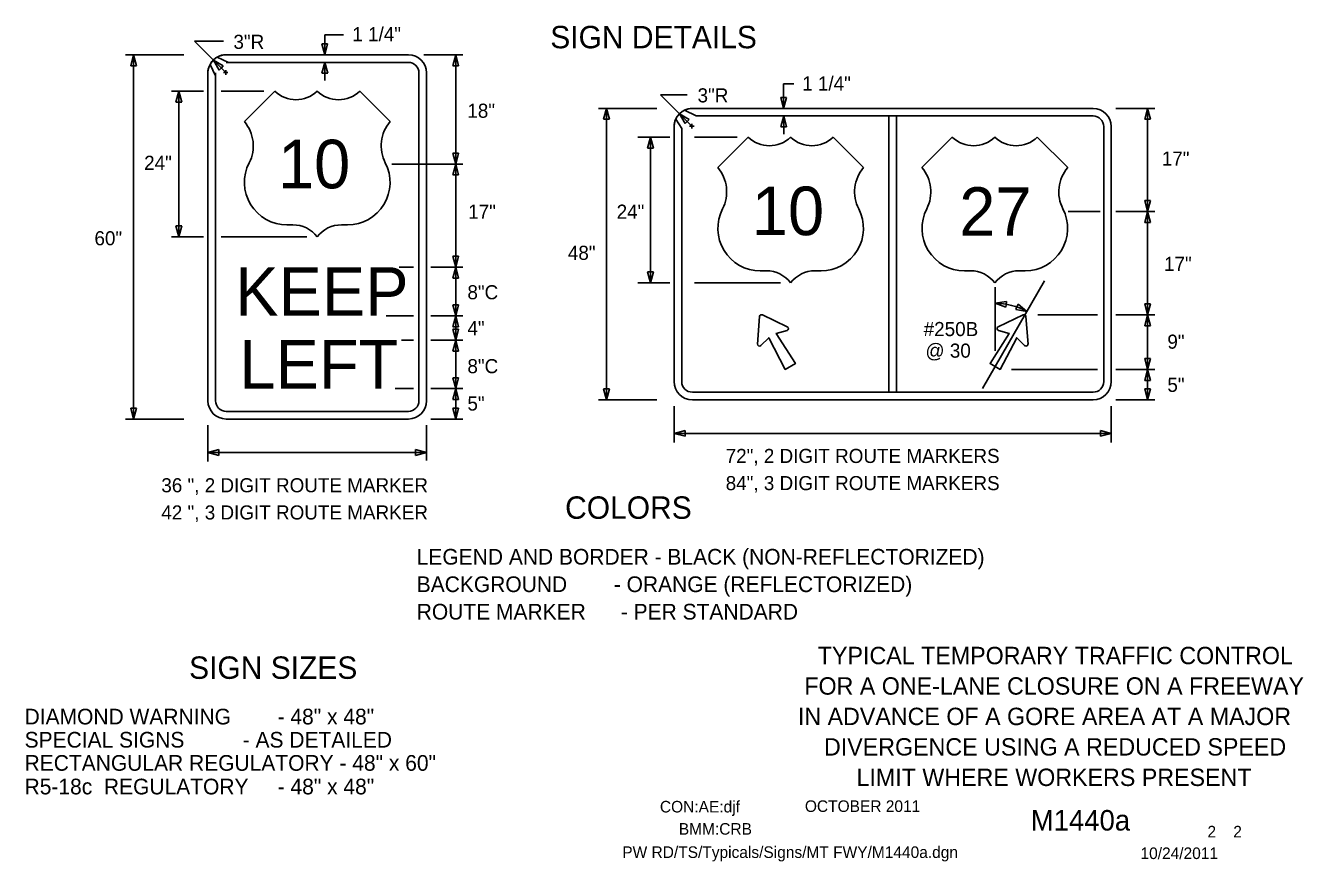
# Model space of a CAD drawing. Extents: x 16731 to 18464, y 5737 to 6974.
# Drawn here: x 17780 to 18464, y 5932 to 6379 of the extents above; entities that cross this region are included whole.
import ezdxf

# ---------------------------------------------------------------- set-up
doc = ezdxf.new("R2010")
doc.units = 0
for name, color, linetype in [('BORDER', 7, 'Continuous'), ('BORDER_SIGNAL_WO', 7, 'Continuous'), ('TRAFFIC_SIGNS_PR', 7, 'Continuous'), ('TYPICAL_EX', 7, 'Continuous'), ('TYPICAL_TEXT_DIMEN_PR', 7, 'Continuous')]:
    doc.layers.add(name, color=color, linetype=linetype)

msp = doc.modelspace()

# ---------------------------------------------------------------- linework, layer by layer
at = {"layer": 'TRAFFIC_SIGNS_PR'}
for p, q in [((17888.74, 6359.64), (17882.64, 6362.38)), ((17887.54, 6363.7), (17985.04, 6363.7)), ((17879.95, 6360.08), (17878.95, 6358.57)), ((17878.98, 6358.5), (17881.85, 6352.46)), ((17985.04, 6359.64), (17887.54, 6359.64)), ((17877.79, 6178.45), (17877.79, 6353.95)), ((17881.85, 6353.95), (17881.85, 6178.45)), ((17990.72, 6178.45), (17990.72, 6353.95)), ((17994.79, 6353.95), (17994.79, 6178.45)), ((18139.01, 6330.95), (18132.78, 6333.97)), ((18137.06, 6335), (18351.56, 6335)), ((18137.06, 6335), (18351.56, 6335)), ((18128.23, 6329.26), (18131.37, 6324.21)), ((18138.99, 6330.94), (18242.28, 6330.94)), ((18351.56, 6330.94), (18139, 6330.94)), ((18242.28, 6330.94), (18242.28, 6183.06)), ((18246.34, 6330.94), (18246.34, 6183.06)), ((18246.34, 6330.94), (18351.56, 6330.94)), ((18127.31, 6325.25), (18127.31, 6188.75)), ((18127.31, 6188.75), (18127.31, 6325.25)), ((18131.37, 6324.2), (18131.37, 6188.75)), ((18131.37, 6324.2), (18131.37, 6188.75)), ((18357.24, 6325.25), (18357.24, 6279.5)), ((18357.25, 6188.75), (18357.25, 6325.25)), ((18361.31, 6325.25), (18361.31, 6188.75)), ((18361.31, 6325.25), (18361.31, 6188.75)), ((18357.24, 6279.5), (18357.24, 6188.75)), ((18174.57, 6224.44), (18187.89, 6218.08)), ((18314.04, 6224.44), (18300.73, 6218.08)), ((18171.91, 6208.86), (18173.06, 6223.57)), ((18316.71, 6208.86), (18315.56, 6223.57)), ((18137.06, 6183.06), (18351.56, 6183.06)), ((18137.06, 6179), (18351.56, 6179)), ((18351.56, 6179), (18137.06, 6179)), ((17887.54, 6172.76), (17985.04, 6172.76)), ((17985.04, 6168.7), (17887.54, 6168.7))]:
    msp.add_line(p, q, dxfattribs=at)
for points in [[(18139, 6330.94), (18138.98, 6330.94)], [(18131.37, 6324.21), (18131.37, 6324.2)], [(18187.73, 6216.11), (18182, 6214.54), (18192.22, 6198.37), (18186.82, 6195.25), (18177.93, 6212.19), (18173.7, 6208.02)], [(18300.89, 6216.11), (18306.61, 6214.54), (18296.4, 6198.37), (18301.79, 6195.25), (18310.69, 6212.19), (18314.91, 6208.02)]]:
    msp.add_lwpolyline(points, dxfattribs=at)
msp.add_lwpolyline([(18242.28, 6330.94), (18246.34, 6330.94), (18246.34, 6183.06), (18242.28, 6183.06)], close=True, dxfattribs=at)
for centre, radius, start, end in [((17887.54, 6353.95), 9.75, 90, 180), ((17886.95, 6356.12), 7.6, 85.58319, 124.53531), ((17985.04, 6353.95), 9.75, 0, 90), ((17884.82, 6354.54), 7.06, 145.86811, 184.82317), ((17888.14, 6364.06), 4.47, 262.2432, 277.7568), ((17985.04, 6353.95), 5.69, 0, 90), ((17876.39, 6353.2), 5.51, 352.24294, 7.75653), ((18137.06, 6325.25), 9.75, 90, 180), ((18137.06, 6325.25), 9.75, 90, 180), ((18136.38, 6328.43), 6.6, 84.11162, 123.06374), ((18351.56, 6325.25), 9.75, 0, 90), ((18351.56, 6325.25), 9.75, 0, 90), ((18133.44, 6325.95), 6.17, 147.60925, 186.56283), ((18138, 6338.12), 7.24, 277.81035, 278.05403), ((18351.56, 6325.25), 5.69, 0, 89.99421), ((18351.56, 6325.25), 5.69, 0, 90), ((18174.12, 6223.49), 1.06, 64.48226, 175.51774), ((18314.5, 6223.49), 1.06, 4.48226, 115.51774), ((18187.43, 6217.13), 1.06, 285.9885, 64.48226), ((18301.18, 6217.13), 1.06, 115.51774, 254.0115), ((18172.97, 6208.78), 1.06, 175.51775, 314.01151), ((18315.65, 6208.78), 1.06, 225.98849, 4.48225), ((18137.06, 6188.75), 9.75, 180, 270), ((18137.06, 6188.75), 9.75, 180, 270), ((18137.06, 6188.75), 5.69, 180, 270), ((18137.06, 6188.75), 5.69, 180, 270), ((18351.56, 6188.75), 9.75, 270, 0), ((18351.56, 6188.75), 5.69, 270, 0), ((18351.56, 6188.75), 9.75, 270, 0), ((18351.56, 6188.75), 5.69, 270, 0), ((17887.54, 6178.45), 9.75, 180, 270), ((17887.54, 6178.45), 5.69, 180, 270), ((17985.04, 6178.45), 5.69, 270, 0), ((17985.04, 6178.45), 9.75, 270, 0)]:
    msp.add_arc(centre, radius, start, end, dxfattribs=at)
at = {"layer": 'TYPICAL_EX'}
for p, q in [((17897.29, 6327.95), (17913.54, 6344.2)), ((17975.29, 6327.95), (17959.04, 6344.2)), ((18150.67, 6303.34), (18166.92, 6319.59)), ((18228.67, 6303.34), (18212.42, 6319.59)), ((18259.95, 6303.34), (18276.2, 6319.59)), ((18337.95, 6303.34), (18321.7, 6319.59)), ((17920.01, 6272.66), (17923.26, 6272.66)), ((17952.56, 6272.66), (17949.31, 6272.66)), ((18173.4, 6248.05), (18176.65, 6248.05)), ((18205.94, 6248.05), (18202.69, 6248.05)), ((18282.67, 6248.05), (18285.92, 6248.05)), ((18315.22, 6248.05), (18311.97, 6248.05))]:
    msp.add_line(p, q, dxfattribs=at)
for centre, radius, start, end in [((17924.91, 6356.03), 16.42, 226.14041, 313.85958), ((17947.66, 6356.04), 16.42, 226.14042, 313.85959), ((17881.88, 6314.94), 20.16, 333.09768, 40.19361), ((17990.69, 6314.94), 20.16, 139.80639, 206.90233), ((18178.3, 6331.42), 16.42, 226.14041, 313.85958), ((18201.04, 6331.43), 16.42, 226.14042, 313.85959), ((18287.57, 6331.42), 16.42, 226.14041, 313.85958), ((18310.32, 6331.43), 16.42, 226.14042, 313.85959), ((17920.05, 6295.38), 22.73, 152.6698, 269.90132), ((17952.52, 6295.38), 22.73, 270.09868, 27.3302), ((18135.27, 6290.33), 20.16, 333.09768, 40.19361), ((18244.07, 6290.33), 20.16, 139.80639, 206.90233), ((18244.55, 6290.33), 20.16, 333.09768, 40.19361), ((18353.35, 6290.33), 20.16, 139.80639, 206.90233), ((18173.44, 6270.77), 22.73, 152.6698, 269.90132), ((18205.9, 6270.77), 22.73, 270.09868, 27.3302), ((18282.71, 6270.77), 22.73, 152.6698, 269.90132), ((18315.18, 6270.77), 22.73, 270.09868, 27.3302), ((17923.3, 6256.38), 16.28, 37.1038, 90.13853), ((17949.27, 6256.38), 16.28, 89.86147, 142.8962), ((18176.69, 6231.77), 16.28, 37.1038, 90.13853), ((18202.65, 6231.77), 16.28, 89.86147, 142.8962), ((18285.97, 6231.77), 16.28, 37.1038, 90.13853), ((18311.93, 6231.77), 16.28, 89.86147, 142.8962)]:
    msp.add_arc(centre, radius, start, end, dxfattribs=at)
at = {"layer": 'TYPICAL_TEXT_DIMEN_PR'}
for p, q in [((17886.16, 6370.98), (17870.5, 6370.98)), ((17870.5, 6370.98), (17880.74, 6360.74)), ((17940.26, 6363.7), (17938.69, 6369.56)), ((17938.69, 6369.56), (17940.26, 6369.56)), ((17940.26, 6374.46), (17940.26, 6363.7)), ((17940.26, 6374.46), (17950.36, 6374.46)), ((17940.26, 6369.56), (17941.83, 6369.56)), ((17941.83, 6369.56), (17940.26, 6363.7)), ((17864.96, 6363.7), (17833.66, 6363.7)), ((17836.43, 6357.84), (17838, 6363.7)), ((17838, 6363.7), (17838, 6168.7)), ((17838, 6363.7), (17839.57, 6357.84)), ((17993.33, 6363.7), (18014.29, 6363.7)), ((18008.82, 6357.84), (18010.39, 6363.7)), ((18010.39, 6363.7), (18010.39, 6305.2)), ((18010.39, 6363.7), (18011.96, 6357.84)), ((17838, 6357.84), (17836.43, 6357.84)), ((17839.57, 6357.84), (17838, 6357.84)), ((17880.74, 6360.74), (17887.3, 6354.19)), ((17883.77, 6355.49), (17880.74, 6360.74)), ((17880.74, 6360.74), (17885.99, 6357.71)), ((17884.88, 6356.6), (17883.77, 6355.49)), ((17885.99, 6357.71), (17884.88, 6356.6)), ((17886.09, 6354.19), (17888.5, 6354.19)), ((17887.3, 6352.98), (17887.3, 6355.4)), ((17938.74, 6353.77), (17940.31, 6359.64)), ((17940.31, 6359.64), (17940.31, 6349.89)), ((17940.31, 6359.64), (17941.88, 6353.77)), ((18010.39, 6357.84), (18008.82, 6357.84)), ((18011.96, 6357.84), (18010.39, 6357.84)), ((17940.31, 6353.77), (17938.74, 6353.77)), ((17941.88, 6353.77), (17940.31, 6353.77)), ((18185.92, 6348.15), (18185.92, 6335)), ((18185.92, 6348.15), (18191.44, 6348.15)), ((17875.41, 6344.2), (17858.29, 6344.2)), ((17860.61, 6338.34), (17862.18, 6344.2)), ((17862.18, 6344.2), (17862.18, 6266.2)), ((17862.18, 6344.2), (17863.75, 6338.34)), ((17907.65, 6344.2), (17884.78, 6344.2)), ((18134.2, 6342.28), (18120.02, 6342.28)), ((18120.02, 6342.28), (18130.17, 6332.14)), ((18185.92, 6335), (18184.34, 6340.86)), ((18184.34, 6340.86), (18185.92, 6340.86)), ((18185.92, 6340.86), (18187.49, 6340.86)), ((18187.49, 6340.86), (18185.92, 6335)), ((17862.18, 6338.34), (17860.61, 6338.34)), ((17863.75, 6338.34), (17862.18, 6338.34)), ((18118.08, 6335), (18086.78, 6335)), ((18089.55, 6329.14), (18091.12, 6335)), ((18091.12, 6335), (18091.12, 6179)), ((18091.12, 6335), (18092.69, 6329.14)), ((18363.68, 6335), (18384.64, 6335)), ((18379.17, 6329.14), (18380.74, 6335)), ((18380.74, 6335), (18380.74, 6279.75)), ((18380.74, 6335), (18382.31, 6329.14)), ((18091.12, 6329.14), (18089.55, 6329.14)), ((18092.69, 6329.14), (18091.12, 6329.14)), ((18130.17, 6332.14), (18136.82, 6325.49)), ((18133.21, 6326.88), (18130.17, 6332.14)), ((18130.17, 6332.14), (18135.43, 6329.1)), ((18134.32, 6327.99), (18133.21, 6326.88)), ((18135.43, 6329.1), (18134.32, 6327.99)), ((18184.39, 6325.07), (18185.96, 6330.94)), ((18184.39, 6325.07), (18185.96, 6330.94)), ((18185.96, 6330.94), (18185.96, 6321.19)), ((18185.96, 6330.94), (18187.53, 6325.07)), ((18185.96, 6330.94), (18187.53, 6325.07)), ((18380.74, 6329.14), (18379.17, 6329.14)), ((18382.31, 6329.14), (18380.74, 6329.14)), ((18135.61, 6325.49), (18138.03, 6325.49)), ((18136.82, 6324.28), (18136.82, 6326.7)), ((18185.96, 6325.07), (18184.39, 6325.07)), ((18185.96, 6325.07), (18184.39, 6325.07)), ((18187.53, 6325.07), (18185.96, 6325.07)), ((18187.53, 6325.07), (18185.96, 6325.07)), ((18124.94, 6319.59), (18107.81, 6319.59)), ((18113.1, 6313.73), (18114.67, 6319.59)), ((18114.67, 6313.73), (18113.1, 6313.73)), ((18114.67, 6319.59), (18114.67, 6241.59)), ((18114.67, 6319.59), (18116.25, 6313.73)), ((18116.25, 6313.73), (18114.67, 6313.73)), ((18161.04, 6319.59), (18138.16, 6319.59)), ((18010.39, 6305.2), (18008.82, 6311.06)), ((18008.82, 6311.06), (18010.39, 6311.06)), ((18010.39, 6311.06), (18011.96, 6311.06)), ((18011.96, 6311.06), (18010.39, 6305.2)), ((17976.18, 6305.2), (18014.29, 6305.2)), ((18008.82, 6299.34), (18010.39, 6305.2)), ((18010.39, 6305.2), (18010.39, 6249.95)), ((18010.39, 6305.2), (18011.96, 6299.34)), ((18010.39, 6299.34), (18008.82, 6299.34)), ((18011.96, 6299.34), (18010.39, 6299.34)), ((18338.12, 6279.75), (18355.27, 6279.75)), ((18363.68, 6279.75), (18384.64, 6279.75)), ((18380.74, 6279.75), (18379.17, 6285.61)), ((18379.17, 6285.61), (18380.74, 6285.61)), ((18379.17, 6273.89), (18380.74, 6279.75)), ((18380.74, 6285.61), (18382.31, 6285.61)), ((18382.31, 6285.61), (18380.74, 6279.75)), ((18380.74, 6279.75), (18380.74, 6224.5)), ((18380.74, 6279.75), (18382.31, 6273.89)), ((18380.74, 6273.89), (18379.17, 6273.89)), ((18382.31, 6273.89), (18380.74, 6273.89)), ((17875.41, 6266.2), (17858.29, 6266.2)), ((17862.18, 6266.2), (17860.61, 6272.06)), ((17860.61, 6272.06), (17862.18, 6272.06)), ((17862.18, 6272.06), (17863.75, 6272.06)), ((17863.75, 6272.06), (17862.18, 6266.2)), ((17930.78, 6266.2), (17884.78, 6266.2)), ((18010.39, 6249.95), (18008.82, 6255.81)), ((18008.82, 6255.81), (18010.39, 6255.81)), ((18010.39, 6255.81), (18011.96, 6255.81)), ((18011.96, 6255.81), (18010.39, 6249.95)), ((17980.11, 6249.95), (17987.8, 6249.95)), ((17997.16, 6249.95), (18014.29, 6249.95)), ((18008.82, 6244.09), (18010.39, 6249.95)), ((18010.39, 6249.95), (18010.39, 6223.95)), ((18010.39, 6249.95), (18011.96, 6244.09)), ((18114.67, 6241.59), (18113.1, 6247.45)), ((18113.1, 6247.45), (18114.67, 6247.45)), ((18114.67, 6247.45), (18116.25, 6247.45)), ((18116.25, 6247.45), (18114.67, 6241.59)), ((18010.39, 6244.09), (18008.82, 6244.09)), ((18011.96, 6244.09), (18010.39, 6244.09)), ((18124.94, 6241.59), (18107.81, 6241.59)), ((18184.16, 6241.59), (18138.16, 6241.59)), ((18292.34, 6185.1), (18325.58, 6242.69)), ((18299.1, 6205.25), (18299.1, 6239.25)), ((18299.12, 6230.69), (18305.12, 6231.65)), ((18305.12, 6231.65), (18304.96, 6230.09)), ((18010.39, 6223.95), (18008.82, 6229.81)), ((18008.82, 6229.81), (18010.39, 6229.81)), ((18010.39, 6229.81), (18011.96, 6229.81)), ((18011.96, 6229.81), (18010.39, 6223.95)), ((18304.8, 6228.53), (18299.12, 6230.69)), ((18304.96, 6230.09), (18304.8, 6228.53)), ((18310.11, 6227.37), (18310.79, 6228.78)), ((18316.08, 6226.24), (18310.11, 6227.37)), ((18310.79, 6228.78), (18311.48, 6230.2)), ((18311.48, 6230.2), (18316.08, 6226.24)), ((18322.05, 6224.5), (18353.92, 6224.5)), ((18363.68, 6224.5), (18384.64, 6224.5)), ((18380.74, 6224.5), (18379.17, 6230.36)), ((18379.17, 6230.36), (18380.74, 6230.36)), ((18379.17, 6218.64), (18380.74, 6224.5)), ((18380.74, 6230.36), (18382.31, 6230.36)), ((18382.31, 6230.36), (18380.74, 6224.5)), ((18380.74, 6224.5), (18380.74, 6195.25)), ((18380.74, 6224.5), (18382.31, 6218.64)), ((17973.1, 6223.95), (17987.8, 6223.95)), ((17997.16, 6223.95), (18014.29, 6223.95)), ((18008.82, 6218.09), (18010.39, 6223.95)), ((18010.39, 6218.09), (18008.82, 6218.09)), ((18010.39, 6223.95), (18010.39, 6210.95)), ((18010.39, 6223.95), (18011.96, 6218.09)), ((18011.96, 6218.09), (18010.39, 6218.09)), ((18380.74, 6218.64), (18379.17, 6218.64)), ((18382.31, 6218.64), (18380.74, 6218.64)), ((17981.45, 6210.95), (17987.8, 6210.95)), ((17997.16, 6210.95), (18014.29, 6210.95)), ((18010.39, 6210.95), (18008.82, 6216.81)), ((18008.82, 6216.81), (18010.39, 6216.81)), ((18008.82, 6205.09), (18010.39, 6210.95)), ((18010.39, 6216.81), (18011.96, 6216.81)), ((18011.96, 6216.81), (18010.39, 6210.95)), ((18010.39, 6210.95), (18010.39, 6184.95)), ((18010.39, 6210.95), (18011.96, 6205.09)), ((18010.39, 6205.09), (18008.82, 6205.09)), ((18011.96, 6205.09), (18010.39, 6205.09)), ((18380.74, 6195.25), (18379.17, 6201.11)), ((18379.17, 6201.11), (18380.74, 6201.11)), ((18380.74, 6201.11), (18382.31, 6201.11)), ((18382.31, 6201.11), (18380.74, 6195.25)), ((18010.39, 6184.95), (18008.82, 6190.81)), ((18008.82, 6190.81), (18010.39, 6190.81)), ((18010.39, 6190.81), (18011.96, 6190.81)), ((18011.96, 6190.81), (18010.39, 6184.95)), ((18307.91, 6195.25), (18353.92, 6195.25)), ((18363.68, 6195.25), (18384.64, 6195.25)), ((18379.17, 6189.39), (18380.74, 6195.25)), ((18380.74, 6195.25), (18380.74, 6179)), ((18380.74, 6195.25), (18382.31, 6189.39)), ((17977.95, 6184.95), (17987.8, 6184.95)), ((17997.16, 6184.95), (18014.29, 6184.95)), ((18008.82, 6179.09), (18010.39, 6184.95)), ((18010.39, 6184.95), (18010.39, 6168.7)), ((18010.39, 6184.95), (18011.96, 6179.09)), ((18091.12, 6179), (18089.55, 6184.86)), ((18089.55, 6184.86), (18091.12, 6184.86)), ((18091.12, 6184.86), (18092.69, 6184.86)), ((18092.69, 6184.86), (18091.12, 6179)), ((18380.74, 6189.39), (18379.17, 6189.39)), ((18380.74, 6179), (18379.17, 6184.86)), ((18379.17, 6184.86), (18380.74, 6184.86)), ((18382.31, 6189.39), (18380.74, 6189.39)), ((18380.74, 6184.86), (18382.31, 6184.86)), ((18382.31, 6184.86), (18380.74, 6179)), ((18010.39, 6179.09), (18008.82, 6179.09)), ((18011.96, 6179.09), (18010.39, 6179.09)), ((18118.08, 6179), (18086.78, 6179)), ((18363.68, 6179), (18380.81, 6179)), ((18363.68, 6179), (18384.64, 6179)), ((18363.68, 6179), (18380.81, 6179)), ((17838, 6168.7), (17836.43, 6174.56)), ((17836.43, 6174.56), (17838, 6174.56)), ((17838, 6174.56), (17839.57, 6174.56)), ((17839.57, 6174.56), (17838, 6168.7)), ((18010.39, 6168.7), (18008.82, 6174.56)), ((18008.82, 6174.56), (18010.39, 6174.56)), ((18010.39, 6174.56), (18011.96, 6174.56)), ((18011.96, 6174.56), (18010.39, 6168.7)), ((18127.31, 6175.65), (18127.31, 6156.09)), ((18361.31, 6175.65), (18361.31, 6156.09)), ((17864.96, 6168.7), (17833.66, 6168.7)), ((17877.79, 6165.35), (17877.79, 6146)), ((17994.79, 6165.35), (17994.79, 6146.46)), ((17997.16, 6168.7), (18014.29, 6168.7)), ((18127.31, 6161.03), (18133.17, 6162.6)), ((18127.31, 6161.03), (18361.31, 6161.03)), ((18133.17, 6159.46), (18127.31, 6161.03)), ((18133.17, 6162.6), (18133.17, 6161.03)), ((18133.17, 6161.03), (18133.17, 6159.46)), ((18355.45, 6161.03), (18355.45, 6162.6)), ((18355.45, 6162.6), (18361.31, 6161.03)), ((18361.31, 6161.03), (18355.45, 6159.46)), ((18355.45, 6159.46), (18355.45, 6161.03)), ((17877.79, 6150.73), (17883.65, 6152.3)), ((17877.79, 6150.73), (17994.79, 6150.73)), ((17883.65, 6149.15), (17877.79, 6150.73)), ((17883.65, 6152.3), (17883.65, 6150.73)), ((17883.65, 6150.73), (17883.65, 6149.15)), ((17988.92, 6150.73), (17988.92, 6152.3)), ((17988.92, 6152.3), (17994.79, 6150.73)), ((17994.79, 6150.73), (17988.92, 6149.15)), ((17988.92, 6149.15), (17988.92, 6150.73))]:
    msp.add_line(p, q, dxfattribs=at)
msp.add_arc((18299.29, 6196.25), 34.39, 60.74521, 90.32117, dxfattribs=at)

# ---------------------------------------------------------------- texts
at = {"layer": 'BORDER'}
for s, p in [('TYPICAL TEMPORARY TRAFFIC CONTROL', (18204.21, 6037.44)), ('FOR A ONE-LANE CLOSURE ON A FREEWAY', (18196.99, 6021.14)), ('IN ADVANCE OF A GORE AREA AT A MAJOR', (18193.54, 6004.84)), ('DIVERGENCE USING A REDUCED SPEED', (18207.52, 5988.54)), ('LIMIT WHERE WORKERS PRESENT', (18224.92, 5972.24))]:
    msp.add_text(s, height=9.3, dxfattribs=at).set_placement(p)
at = {"layer": 'BORDER_SIGNAL_WO'}
for s, height, p in [('CON:AE:djf  ', 6.2, (18119.69, 5958.06)), ('    OCTOBER 2011    ', 6.2, (18188.08, 5958.34)), ('    M1440a   ', 11, (18301.86, 5948.38)), ('BMM:CRB   ', 6.2, (18129.81, 5946.17)), (' 2    2 ', 6.2, (18410.45, 5944.7)), ('PW RD/TS/Typicals/Signs/MT FWY/M1440a.dgn      ', 6.2, (18099.55, 5933.71)), ('10/24/2011    ', 6.2, (18376.93, 5933.13))]:
    msp.add_text(s, height=height, dxfattribs=at).set_placement(p)
at = {"layer": 'TRAFFIC_SIGNS_PR'}
for s, p in [('10', (17915.26, 6292.2)), ('10', (18168.91, 6267.13)), ('27', (18279.91, 6266.77)), ('KEEP', (17892.39, 6223.95)), ('LEFT', (17894.62, 6184.95))]:
    msp.add_text(s, height=26, dxfattribs=at).set_placement(p)
at = {"layer": 'TYPICAL_TEXT_DIMEN_PR'}
for s, height, p in [('1 1/4"', 7.55, (17955.06, 6370.95)), ('SIGN DETAILS', 12, (18061.01, 6367.17)), ('3"R', 7.55, (17891.42, 6366.86)), ('1 1/4"', 7.55, (18195.84, 6344.57)), ('3"R', 7.55, (18139.84, 6338.2)), ('18"', 7.55, (18016.63, 6329.97)), ('24"', 7.55, (17843.63, 6302.08)), ('17"', 7.55, (18388.32, 6304.36)), ('17"', 7.55, (18017.08, 6275.92)), ('24"', 7.55, (18096.53, 6275.92)), ('60"', 7.55, (17817.03, 6261.71)), ('48"', 7.55, (18070.42, 6253.9)), ('17"', 7.55, (18389.52, 6248)), ('8"C', 7.55, (18016.66, 6232.8)), ('4" ', 7.55, (18016.66, 6213.54)), ('#250B', 7.55, (18260.87, 6213.09)), ('9"', 7.55, (18391.3, 6206.34)), ('@ 30', 7.55, (18261.81, 6201.54)), ('8"C', 7.55, (18016.66, 6193.22)), ('5"', 7.55, (18391.3, 6183.24)), ('5" ', 7.55, (18016.66, 6173.24)), ('72", 2 DIGIT ROUTE MARKERS', 7.55, (18154.89, 6145.16)), ('36 ", 2 DIGIT ROUTE MARKER', 7.55, (17852.83, 6129.46)), ('84", 3 DIGIT ROUTE MARKERS', 7.55, (18154.89, 6130.61)), ('42 ", 3 DIGIT ROUTE MARKER', 7.55, (17852.83, 6114.91)), ('COLORS', 12, (18068.95, 6115.28)), ('LEGEND AND BORDER - BLACK (NON-REFLECTORIZED)', 8.4, (17989.53, 6090.75)), ('BACKGROUND        - ORANGE (REFLECTORIZED)', 8.4, (17989.53, 6076.05)), ('ROUTE MARKER      - PER STANDARD', 8.4, (17989.53, 6061.35)), ('SIGN SIZES', 12, (17867.69, 6029.59)), ('DIAMOND WARNING        - 48" x 48"', 8.4, (17779.65, 6005.19)), ('SPECIAL SIGNS          - AS DETAILED', 8.4, (17779.65, 5992.79)), ('RECTANGULAR REGULATORY - 48" x 60"', 8.4, (17779.65, 5980.39)), ('R5-18c  REGULATORY     - 48" x 48"', 8.4, (17779.65, 5967.74))]:
    msp.add_text(s, height=height, dxfattribs=at).set_placement(p)

doc.saveas('drawing.dxf')
